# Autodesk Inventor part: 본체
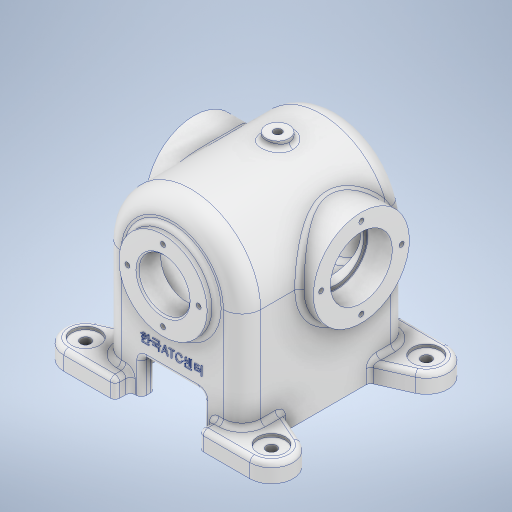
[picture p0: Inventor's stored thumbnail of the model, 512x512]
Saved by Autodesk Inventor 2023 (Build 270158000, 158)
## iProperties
Created: 2024-09
Part Number: 본체
Material: 알루미늄 6061
Document SubType Name: Modeling
Designer: asung
Density: 2.7 g/cm^3
Appearance: 알루미늄 - 평지
Author: asung
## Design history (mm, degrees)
sketch "스케치1"
  geometry: C1 r 45 at (0, 0); 1 further point
  constraints: 1 centre point, 1 coincident
  dimensions: "d0" = 90 diameter of C1
extrude "돌출1" new body sketch "스케치1" stored distance "d1" = 108; taper "d2" = 0 deg
sketch "스케치2"
  geometry: C1 r 28.5 at (0, 0); 1 further point
  constraints: 1 centre point, 1 coincident
  dimensions: "d3" = 57 diameter of C1
extrude "돌출2" join sketch "스케치2" distance "d4" = 6; taper "d5" = 0 deg
node "작업 평면1"
sketch "스케치6"
  geometry: L1 (-54, 31)-(54, 31); L2 (54, 31)-(54, 0); L3 (54, 0)-(-54, 0); L4 (-54, 0)-(-54, 31); 2 further points
  constraints: 8 end point, 2 parallel, 1 coincident, 1 horizontal, 1 midpoint, 1 perpendicular
  dimensions: "d9" = 108 distance of L2.end L3.end; "d10" = 31 distance of L1.end L2.end
revolve "회전1" sketch "스케치6" stored, may be unused: angle "d11" = 90 deg
sketch "스케치8"
  geometry: L1 (45, -54)-(-45, -54) reference; L2 (-45, -54)-(-45, 54) reference; L3 (-45, 54)-(-28.5, 54) reference; L4 (-28.5, 54)-(-28.5, 60) reference; L5 (-28.5, 60)-(28.5, 60) reference; L6 (28.5, 60)-(28.5, 54) reference; L7 (28.5, 54)-(45, 54) reference; L8 (45, 54)-(45, -54) reference; L9 (28.5, 60)-(-28.5, 60) reference; L10 (0, 60)-(0, -45); L11 (0, -45)-(33, -45); L12 (36, -42)-(36, 42); L13 (33, 45)-(16.5, 45); L14 (16.5, 45)-(16.5, 60); A1 r 3 centre (33, -42) between (33, -45) and (36, -42); A2 r 3 centre (33, 42) between (36, 42) and (33, 45); 4 further points
  constraints: 10 end point, 4 perpendicular, 4 point on circle, 4 tangent, 2 centre point, 2 midpoint, 1 equal radius, 1 point on line, 1 vertical
  dimensions: "d20" = 9 vertical distance of L1.start L10.end; "d21" = 9 distance between parallel lines of L12 L8; "d22" = 9 distance between parallel lines of L7 L13; "d23" = 16.5 distance of point (0, 60) L14.end; "d24" = 3 radius of A1
revolve "회전2" sketch "스케치8" stored, may be unused: angle "d25" = 90 deg
chamfer "모따기1" distance "d26" = 1; stored, may be unused: second distance "d27" = 2, angle "d28" = 45 deg
fillet "모깎기1" dims "d29" = 3
sketch "스케치12"
  geometry: L1 (0, 0)-(0, -76); L2 (-45, -76)-(45, -76); L3 (-45, -76)-(-45, 0); L4 (45, -76)-(45, 0); C1 r 36 at (0, 0) reference; C2 r 45 at (0, 0) reference; C3 r 31.5 at (0, 0) reference; A1 r 45 centre (0, 0) between (-45, 0) and (45, 0) reference; 2 further points
  constraints: 8 end point, 2 point on circle, 1 horizontal, 1 midpoint, 1 vertical
  dimensions: "d42" = 76 distance of L1.end L1.start; "d44" = 90 distance of L2.start L2.end; "d45" = 76 distance of L2.start L3.end; "d46" = 76 distance of L2.end L4.end
extrude "돌출4" join sketch "스케치12" distance "d47" = 108; taper "d48" = 0 deg
node "작업 평면4"
sketch "스케치15"
  geometry: L1 (90, 0)-(0, 0) reference; C1 r 7.5 at (45, -68); 2 further points
  constraints: 1 centre point, 1 midpoint, 1 vertical alignment
  dimensions: "d60" = 15 diameter of C1; "d61" = 68 distance of C1.centre point (45, 0)
extrude "돌출5" join sketch "스케치15" stored distance "d62" = 108; taper "d63" = 0 deg
sketch "스케치16"
  geometry: C1 r 7.5 at (0, 0) reference; 2 further points
  constraints: 1 coincident
hole "구멍3" sketch "스케치16" at (0, 0) diameter "d64" = 5.1881; stored, may be unused: countersink angle "d68" = 90 deg, drill point angle "d70" = 0 deg; dims "d65" = 300, "d66" = 4, "d67" = 2, "d69" = 16
sketch "스케치18" dims "d88" = 14, "d90" = 14
  geometry: L1 (-15, 10)-(105, 10); L2 (119, -4)-(119, -104); L3 (105, -118)-(-15, -118); L4 (-29, -104)-(-29, -104); L5 (-29, 10)-(119, -118); L6 (119, 10)-(-29, -118); L7 (81, -12)-(9, -12) reference; L8 (0, 0)-(90, 0) reference; L9 (0, 0)-(0, -108) reference; L10 (90, -108)-(0, -108) reference; L11 (90, 0)-(90, -108) reference; L12 (25, 10)-(65, 10); L13 (65, 10)-(65, -14); L14 (65, -14)-(25, -14); L15 (25, -14)-(25, 10); L16 (25, -118)-(65, -118); L17 (65, -118)-(65, -90); L18 (65, -90)-(25, -90); L19 (25, -90)-(25, -118); L20 (-29, -4)-(-29, -4); L21 (0, -82)-(-20.693, -91.21); L22 (0, -26)-(-20.693, -16.79); L23 (45, -118)-(45, 10); L24 (0, -108)-(90, -108) reference; L25 (90, -82)-(110.693, -91.21); L26 (90, -26)-(110.693, -16.79); C1 r 2.594 at (45, -68) reference; A1 r 14 centre (-15, -4) between (-15, 10) and (-29, -4); A2 r 14 centre (105, -4) between (119, -4) and (105, 10); A3 r 14 centre (105, -104) between (105, -118) and (119, -104); A4 r 14 centre (-15, -104) between (-29, -104) and (-15, -118); 15 further points
  constraints: 40 end point, 11 point on line, 9 point on circle, 8 tangent, 6 midpoint, 6 parallel, 6 symmetric about line, 4 centre point, 4 perpendicular, 3 equal radius, 3 horizontal, 3 vertical, 2 coincident, 14 other
  dimensions: "d71" = 148 distance of L5.end L6.end; "d72" = 128 distance of L6.start L5.end; "d73" = 14 radius of A1 (derived); "d75" = 40 distance of L13.end L14.end; "d76" = 24 distance of L12.end L13.end; "d77" = 40 distance of L18.end L17.end; "d78" = 28 distance of L17.end L16.end; "d89" = 36 vertical distance of L3.end L21.start; "d91" = 36 vertical distance of L22.start L1.start; "d181" = 36 distance from line of L26.start L1 (derived); "d182" = 36 distance from line of L3 L25.start (derived)
extrude "돌출6" join sketch "스케치18" distance "d92" = 12; taper "d93" = 0 deg
node "작업 평면5"
sketch "스케치21"
  geometry: L1 (-73.077, -64)-(-45, -64) reference; L2 (-45, -64)-(-45, 0) reference; L3 (45, 0)-(45, -64) reference; L4 (45, -64)-(73.077, -64) reference; L5 (73.077, -64)-(73.077, -76) reference; L6 (73.077, -76)-(-73.077, -76) reference; L7 (-73.077, -76)-(-73.077, -64) reference; L8 (-36, -76)-(36, -76); L9 (36, -76)-(36, -45); L10 (36, -45)-(-36, -45); L11 (-36, -45)-(-36, -76); C1 r 16.5 at (0, 0) reference; C2 r 33 at (0, 0) reference; A1 r 45 centre (0, 0) between (45, 0) and (-45, 0) reference; 4 further points
  constraints: 8 end point, 2 midpoint, 2 parallel, 1 horizontal, 1 perpendicular
  dimensions: "d97" = 72 distance of L10.end L9.end; "d98" = 31 distance of L9.end L8.end
extrude "돌출7" cut sketch "스케치21" distance "d99" = 90; taper "d100" = 0 deg
fillet "모깎기3" dims "d101" = 3
sketch "스케치22"
  geometry: 1 further point
sketch "스케치23"
  geometry: L1 (72, 0)-(0, 0) reference; L2 (0, 0)-(0, -90) reference; L3 (0, -90)-(72, -90) reference; L4 (72, 0)-(72, -90) reference; L5 (0, -90)-(0, 0) reference; L6 (0, 0)-(72, 0) reference; L7 (72, 0)-(72, -90) reference; L8 (72, -90)-(0, -90) reference; L9 (56, -99)-(16, -99) reference; L10 (56, -99)-(56, -109) reference; L11 (56, -109)-(96, -109) reference; L12 (101.693, -82.21)-(81, -73) reference; L13 (81, -17)-(81, -73) reference; L14 (81, -17)-(101.693, -7.79) reference; L15 (96, 19)-(56, 19) reference; L16 (56, 19)-(56, 9) reference; L17 (16, 9)-(56, 9) reference; L18 (16, 9)-(16, 19) reference; L19 (16, 19)-(-24, 19) reference; L20 (-29.693, -7.79)-(-9, -17) reference; L21 (-9, -17)-(-9, -73) reference; L22 (-9, -73)-(-29.693, -82.21) reference; L23 (-24, -109)-(16, -109) reference; L24 (16, -109)-(16, -99) reference; C1 r 2.594 at (36, -59) reference; C2 r 7.5 at (36, -59); C3 r 2.594 at (36, -59) reference; A1 r 14 centre (96, -95) between (96, -109) and (101.693, -82.21) reference; A2 r 14 centre (96, 5) between (101.693, -7.79) and (96, 19) reference; A3 r 14 centre (-24, 5) between (-24, 19) and (-29.693, -7.79) reference; A4 r 14 centre (-24, -95) between (-29.693, -82.21) and (-24, -109) reference; 3 further points
  constraints: 1 centre point, 1 coincident, 1 horizontal alignment, 1 other
  dimensions: "d103" = 15 diameter of C2
extrude "돌출8" join sketch "스케치23" distance "d104" = 4; taper "d105" = 0 deg
fillet "모깎기4" dims "d106" = 3
sketch "스케치24"
  geometry: L1 (-45, -64)-(-20, -64) reference; L2 (-20, -64)-(-20, -76) reference; L3 (-20, -76)-(20, -76) reference; L4 (20, -76)-(20, -64) reference; L5 (20, -64)-(45, -64) reference; L6 (45, -64)-(45, 0) reference; L7 (-45, 0)-(-45, -64) reference; L8 (-20, -76)-(20, -76); L9 (20, -76)-(20, -53); L10 (20, -53)-(-20, -53); L11 (-20, -53)-(-20, -76); C1 r 31.5 at (0, 0) reference; A1 r 45 centre (0, 0) between (45, 0) and (-45, 0) reference; 4 further points
  constraints: 8 end point, 2 midpoint, 2 parallel, 1 horizontal, 1 perpendicular
  dimensions: "d107" = 40 distance of L10.end L9.end; "d108" = 23 distance of L9.end L8.end
extrude "돌출9" cut sketch "스케치24" extent not by distance; stored distance "d109" = 4; taper "d110" = 0 deg
fillet "모깎기5" dims "d111" = 3
fillet "모깎기6" dims "d112" = 12
fillet "모깎기7" dims "d113" = 12
fillet "모깎기8" dims "d114" = 3
sketch "스케치25"
  geometry: L1 (-65, 12)-(-53, 12) reference; L2 (-53, 12)-(-53, 76) reference; L3 (-65, 76)-(-53, 76) reference; L4 (-65, 76)-(-65, 12) reference; L5 (25, 76)-(13, 76) reference; L6 (13, 76)-(13, 12) reference; L7 (13, 12)-(25, 12) reference; L8 (25, 12)-(25, 76) reference; L9 (-53, 12)-(-53, 76) reference; L10 (-53, 12)-(-40, 12) reference; L11 (-40, 12)-(-40, 23) reference; L12 (-40, 23)-(0, 23) reference; L13 (0, 23)-(0, 12) reference; L14 (0, 12)-(13, 12) reference; L15 (13, 76)-(13, 12) reference; L16 (-65, 12)-(-47, 12); L17 (-47, 12)-(-47, 0); L18 (-47, 0)-(-65, 0); L19 (-65, 0)-(-65, 12); L20 (25, 12)-(7, 12); L21 (7, 12)-(7, 0); L22 (7, 0)-(25, 0); L23 (25, 0)-(25, 12); L24 (7, 12)-(-47, 12); L25 (-47, 12)-(-47, 0); L26 (-47, 0)-(7, 0); L27 (7, 0)-(7, 12); C1 r 31.5 at (-20, 76) reference; A1 r 33 centre (-20, 76) between (13, 76) and (-53, 76) reference; 6 further points
  constraints: 24 end point, 6 parallel, 3 horizontal, 3 perpendicular
  dimensions: "d115" = 18 distance of L17.end L18.end; "d116" = 12 distance of L16.end L17.end; "d117" = 18 distance of L22.end L21.end; "d118" = 12 distance of L21.end L20.end
extrude "돌출10" cut sketch "스케치25" distance "d119" = 10; taper "d120" = 0 deg
fillet "모깎기9" dims "d121" = 3
fillet "모깎기10" dims "d122" = 3
fillet "모깎기11" dims "d123" = 3
sketch "스케치26"
  geometry: A1 r 11 centre (105, 4) between (105, -7) and (109.473, 14.05) reference; A2 r 11 centre (105, 104) between (109.473, 93.95) and (105, 115) reference; A3 r 11 centre (-15, 4) between (-19.473, 14.05) and (-15, -7) reference; A4 r 11 centre (-15, 104) between (-15, 115) and (-19.473, 93.95) reference; 5 further points
  constraints: 4 coincident
hole "구멍4" sketch "스케치26" at (105, 4), (105, 104), (-15, 4), (-15, 104) diameter "d124" = 6.6; stored, may be unused: countersink angle "d128" = 90 deg, drill point angle "d130" = 0 deg; dims "d125" = 12, "d126" = 18, "d127" = 2, "d129" = 12
sketch "스케치27"
  geometry: L1 (0, 0)-(0, 23); 1 further point
  constraints: 2 end point, 1 coincident, 1 vertical
  dimensions: "d131" = 23 distance of L1.start L1.end
hole "구멍5" sketch "스케치27" at (0, 23) diameter "d132" = 3.242; stored, may be unused: countersink angle "d136" = 90 deg, drill point angle "d138" = 118 deg; dims "d133" = 8, "d134" = 18, "d135" = 2, "d137" = 10
fillet "모깎기12" dims "d153" = 3
sketch "스케치29"
  geometry: C1 r 31 at (0, 0) reference; 2 further points
  constraints: 1 coincident
hole "구멍7" sketch "스케치29" at (0, 0) diameter "d157" = 35; stored, may be unused: countersink angle "d161" = 90 deg, drill point angle "d163" = 0 deg; dims "d158" = 6, "d159" = 40, "d160" = 16, "d162" = 54
sketch "스케치30"
  geometry: L1 (0, 0)-(0, 26); C1 r 20 at (0, 0) reference; C2 r 31 at (0, 0) reference; 1 further point
  constraints: 2 end point, 1 vertical
  dimensions: "d164" = 26 distance of L1.start L1.end
hole "구멍8" sketch "스케치30" at (0, 26) diameter "d165" = 3.242; stored, may be unused: countersink angle "d169" = 90 deg, drill point angle "d171" = 118 deg; dims "d166" = 8, "d167" = 40, "d168" = 16, "d170" = 10
fillet "모깎기13" dims "d175" = 0.3
sketch "스케치31"
  geometry: L1 (-20, -76)-(-23, -76) reference; L2 (60, -76)-(74, -76) reference; L3 (60, -76)-(30, -76) reference; 5 further points
  constraints: 2 midpoint, 1 vertical alignment, 1 other
  dimensions: "d178" = 35 distance from line of L3 point (0, -41)
feature "엠보싱1" sketch "스케치31" dims "d179" = 0.5, "d180" = 0
fillet "모깎기14" dims "d183" = 3
fillet "모깎기15" dims "d184" = 3
feature "Ҫ耀Ҭ耀Ү耀Ұ耀Ҳ耀Ҵ耀Ҷ耀Ҹ耀" dims "d0" = 90, "d1" = 108, "d2" = 0, "d3" = 57, "d4" = 6, "d5" = 0, "d8" = -74, "d9" = 108, "d10" = 31, "d11" = 90 deg, "d20" = 9, "d21" = 9, "d22" = 9, "d23" = 16.5, "d24" = 3, "d25" = 90 deg, "d26" = 1, "d27" = 2, "d28" = 45 deg, "d29" = 3, "d42" = 76, "d44" = 90, "d45" = 76, "d46" = 76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
node "솔리드1"
mirror "미러3"
mirror "미러4"
pattern_circular "원형 패턴2" dims angle "d151" = 360 deg
mirror "미러6"
pattern_circular "원형 패턴3" dims angle "d173" = 360 deg
mirror "미러7"
node "투영된 루프1"
node "투영된 루프3"
node "투영된 루프5"
node "투영된 루프6"
node "투영된 루프7"
node "투영된 루프8"
node "투영된 루프9"
node "투영된 루프10"
node "투영된 루프11"
node "절단 모서리 투영1"
node "절단 모서리 투영3"
feature "A9D066F2-1C7D-4E18-AEED-F7BC21143FA4" dims "d64" = 5.1881, "d65" = 300, "d66" = 4, "d67" = 2, "d68" = 90 deg, "d69" = 16, "d70" = 0
